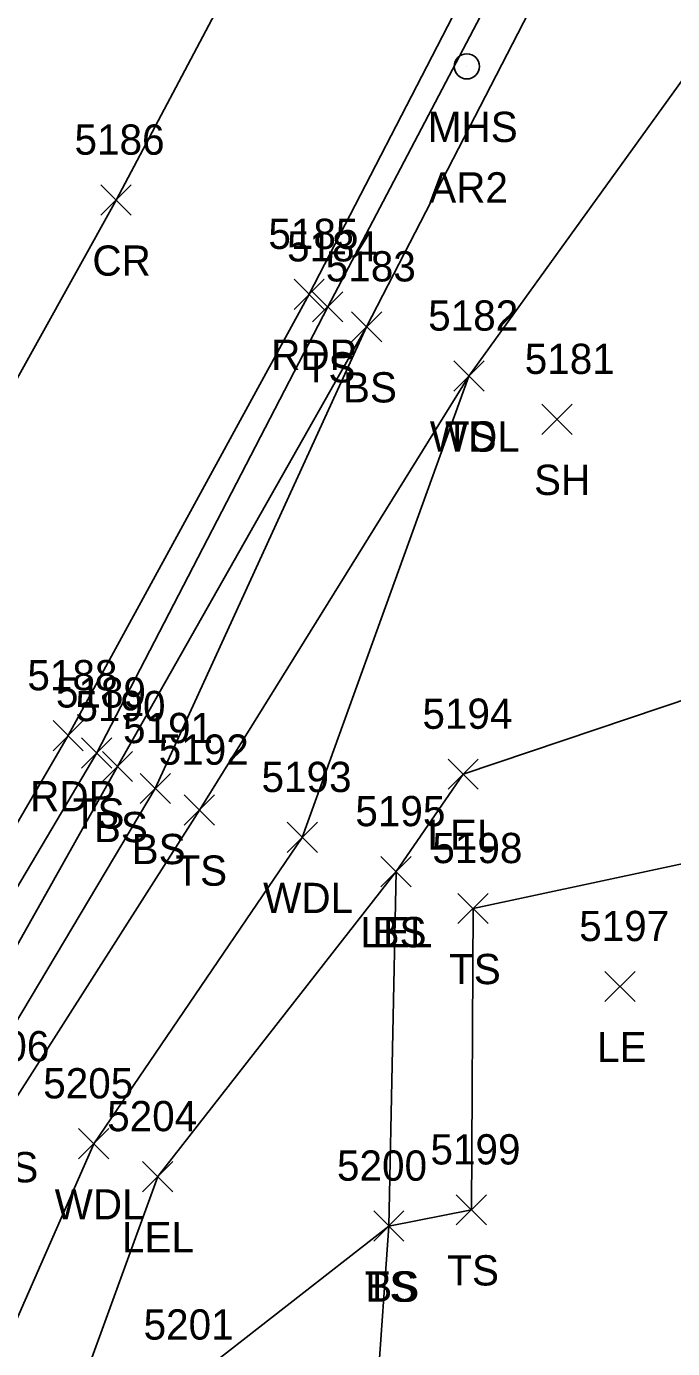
# Model space of a CAD drawing. Extents: x 1678863 to 1683592, y 407783 to 418211.
# Drawn here: x 1679859 to 1679901.7, y 411536.4 to 411623.8 of the extents above; entities that cross this region are included whole.
import ezdxf

# ---------------------------------------------------------------- set-up
doc = ezdxf.new("R2010")
doc.units = 0
for name, color, linetype in [('L_A', 7, 'Continuous'), ('L_I', 7, 'Continuous'), ('L_TIC', 7, 'Continuous'), ('LARO', 7, 'Continuous'), ('LAWA', 7, 'Continuous'), ('LELB', 7, 'Continuous'), ('P_A', 7, 'Continuous'), ('P_I', 7, 'Continuous'), ('P_TIC', 7, 'Continuous'), ('PET', 7, 'Continuous'), ('PRC', 7, 'Continuous'), ('U_A', 7, 'Continuous'), ('U_C', 7, 'Continuous'), ('USMH', 7, 'Continuous')]:
    doc.layers.add(name, color=color, linetype=linetype)

msp = doc.modelspace()

# ---------------------------------------------------------------- linework, layer by layer
at = {"layer": 'L_TIC'}
for points in [[(1679877.886, 411604.221), (1679879.886, 411606.221)], [(1679879.886, 411604.221), (1679877.886, 411606.221)], [(1679880.444, 411602.897), (1679882.444, 411604.897)], [(1679882.444, 411602.897), (1679880.444, 411604.897)], [(1679880.444, 411602.897), (1679882.444, 411604.897)], [(1679882.444, 411602.897), (1679880.444, 411604.897)], [(1679887.208, 411599.645), (1679889.208, 411601.645)], [(1679889.208, 411599.645), (1679887.208, 411601.645)], [(1679887.208, 411599.645), (1679889.208, 411601.645)], [(1679889.208, 411599.645), (1679887.208, 411601.645)], [(1679893.02, 411596.782), (1679895.02, 411598.782)], [(1679895.02, 411596.782), (1679893.02, 411598.782)], [(1679862.627, 411574.73), (1679864.627, 411576.73)], [(1679864.627, 411574.73), (1679862.627, 411576.73)], [(1679863.994, 411573.831), (1679865.994, 411575.831)], [(1679865.994, 411573.831), (1679863.994, 411575.831)], [(1679886.828, 411573.324), (1679888.828, 411575.324)], [(1679888.828, 411573.324), (1679886.828, 411575.324)], [(1679866.487, 411572.377), (1679868.487, 411574.377)], [(1679868.487, 411572.377), (1679866.487, 411574.377)], [(1679869.409, 411570.95), (1679871.409, 411572.95)], [(1679871.409, 411570.95), (1679869.409, 411572.95)], [(1679876.2, 411569.144), (1679878.2, 411571.144)], [(1679878.2, 411569.144), (1679876.2, 411571.144)], [(1679882.398, 411566.885), (1679884.398, 411568.885)], [(1679884.398, 411566.885), (1679882.398, 411568.885)], [(1679882.398, 411566.885), (1679884.398, 411568.885)], [(1679884.398, 411566.885), (1679882.398, 411568.885)], [(1679887.485, 411564.444), (1679889.485, 411566.444)], [(1679889.485, 411564.444), (1679887.485, 411566.444)], [(1679897.183, 411559.29), (1679899.183, 411561.29)], [(1679899.183, 411559.29), (1679897.183, 411561.29)], [(1679862.425, 411548.891), (1679864.425, 411550.891)], [(1679864.425, 411548.891), (1679862.425, 411550.891)], [(1679866.649, 411546.722), (1679868.649, 411548.722)], [(1679868.649, 411546.722), (1679866.649, 411548.722)], [(1679887.367, 411544.524), (1679889.367, 411546.524)], [(1679889.367, 411544.524), (1679887.367, 411546.524)], [(1679881.917, 411543.451), (1679883.917, 411545.451)], [(1679883.917, 411543.451), (1679881.917, 411545.451)], [(1679881.917, 411543.451), (1679883.917, 411545.451)], [(1679883.917, 411543.451), (1679881.917, 411545.451)]]:
    msp.add_lwpolyline(points, dxfattribs=at)
at = {"layer": 'LARO'}
msp.add_lwpolyline([(1679907.503, 411580.963), (1679887.828, 411574.324), (1679883.398, 411567.885), (1679867.649, 411547.722), (1679859.704, 411525.868), (1679858.597, 411519.07), (1679856.94, 411496.975)], dxfattribs=at)
at = {"layer": 'LAWA'}
msp.add_lwpolyline([(1680004.249, 411785.464), (1679976.905, 411753.096), (1679958.04, 411720.983), (1679943.677, 411696.76), (1679930.592, 411672.976), (1679924.115, 411664.991), (1679923.082, 411652.999), (1679912.44, 411634.306), (1679888.208, 411600.645), (1679877.2, 411570.144), (1679863.425, 411549.891), (1679852.513, 411525.045), (1679850.419, 411519.807), (1679839.824, 411505.441), (1679830.057, 411470.344), (1679799.337, 411443.025), (1679785.885, 411428.013), (1679782.745, 411411.852), (1679769.412, 411389.894), (1679761.729, 411378.805), (1679757.565, 411369.696), (1679753.345, 411358.456)], dxfattribs=at)
at = {"layer": 'LELB'}
for points in [[(1679916.516, 411674.282), (1679909.814, 411664.074), (1679898.356, 411642.317), (1679878.886, 411605.221), (1679863.627, 411575.73), (1679852.287, 411556.618), (1679829.81, 411517.044), (1679806.876, 411482.918), (1679785.941, 411449.002), (1679780.561, 411439.673)], [(1679912.886, 411662.567), (1679900.371, 411640.66), (1679881.444, 411603.897), (1679864.994, 411574.831), (1679854.205, 411555.646), (1679832.273, 411515.522), (1679808.936, 411481.732), (1679786.663, 411448.529), (1679780.561, 411439.673)], [(1679881.444, 411603.897), (1679867.487, 411573.377), (1679855.963, 411554.047), (1679841.116, 411527.101), (1679850.419, 411519.807), (1679858.597, 411519.07)], [(1679888.208, 411600.645), (1679870.409, 411571.95), (1679857.937, 411552.344), (1679845.658, 411527.058), (1679852.513, 411525.045), (1679859.704, 411525.868)], [(1679904.651, 411568.894), (1679888.485, 411565.444), (1679888.367, 411545.524), (1679882.917, 411544.451), (1679869.489, 411533.946), (1679866.945, 411496.861)], [(1679883.398, 411567.885), (1679882.917, 411544.451), (1679881.382, 411522.595)]]:
    msp.add_lwpolyline(points, dxfattribs=at)
at = {"layer": 'P_TIC'}
for points in [[(1679863.901, 411611.276), (1679865.901, 411613.276)], [(1679865.901, 411611.276), (1679863.901, 411613.276)], [(1679876.654, 411605.046), (1679878.654, 411607.046)], [(1679878.654, 411605.046), (1679876.654, 411607.046)], [(1679860.735, 411575.871), (1679862.735, 411577.871)], [(1679862.735, 411575.871), (1679860.735, 411577.871)]]:
    msp.add_lwpolyline(points, dxfattribs=at)
at = {"layer": 'PET'}
msp.add_lwpolyline([(1679896.744, 411643.036), (1679877.654, 411606.046), (1679861.735, 411576.871), (1679850.587, 411557.758), (1679827.264, 411518.541), (1679805.428, 411483.788), (1679784.241, 411450.107), (1679753.752, 411395.632), (1679739.592, 411364.36), (1679726.3, 411333.813), (1679713.565, 411299.828), (1679702.729, 411266.533), (1679688.629, 411217.516), (1679676.207, 411170.056), (1679662.503, 411116.261), (1679650.516, 411067.532), (1679638.184, 411018.282), (1679627.73, 410974.874), (1679616.699, 410931.335), (1679604.861, 410884.116), (1679594.891, 410843.787), (1679584.861, 410799.849)], dxfattribs=at)
at = {"layer": 'PRC'}
msp.add_lwpolyline([(1679884.423, 411649.113), (1679864.901, 411612.276), (1679849.333, 411584.209), (1679838.181, 411564.727), (1679814.629, 411525.581), (1679793.157, 411491.355), (1679772.018, 411456.738), (1679754.801, 411427.353), (1679741.755, 411402.459), (1679725.907, 411369.83), (1679712.559, 411339.148), (1679697.19, 411297.012), (1679684.615, 411257.055), (1679672.39, 411213.459), (1679661.84, 411172.032), (1679650.126, 411125.856), (1679638.584, 411078.327), (1679624.742, 411022.941), (1679613.907, 410978.688), (1679602.728, 410933.896), (1679590.952, 410887.12), (1679580.877, 410845.972), (1679570.755, 410804.026)], dxfattribs=at)
at = {"layer": 'USMH'}
for p, q in [((1679888.071, 411621.116), (1679888.071, 411621.116)), ((1679888.905, 411621.116), (1679888.905, 411621.116))]:
    msp.add_line(p, q, dxfattribs=at)
msp.add_circle((1679888.071, 411621.116), 0.833, dxfattribs=at)

# ---------------------------------------------------------------- texts
at = {"layer": 'L_A'}
for s, p in [('TS', (1679877.296, 411600.221)), ('BS', (1679879.885, 411598.897)), ('BS', (1679879.885, 411598.897)), ('WDL', (1679885.625, 411595.645)), ('TS', (1679886.618, 411595.645)), ('SH', (1679892.508, 411592.782)), ('TS', (1679862.036, 411570.73)), ('BS', (1679863.435, 411569.831)), ('LEL', (1679885.466, 411569.324)), ('BS', (1679865.928, 411568.377)), ('TS', (1679868.818, 411566.95)), ('WDL', (1679874.617, 411565.144)), ('LEL', (1679881.035, 411562.885)), ('BS', (1679881.839, 411562.885)), ('TS', (1679886.895, 411560.444)), ('LE', (1679896.671, 411555.29)), ('TS', (1679856.346, 411547.344)), ('WDL', (1679860.842, 411544.891)), ('LEL', (1679865.287, 411542.722)), ('TS', (1679886.776, 411540.524)), ('TS', (1679881.326, 411539.451)), ('BS', (1679881.358, 411539.451))]:
    msp.add_text(s, height=2, dxfattribs=at).set_placement(p)
at = {"layer": 'L_I'}
for s, p in [('5184', (1679876.193, 411608.221)), ('5183', (1679878.751, 411606.897)), ('5183', (1679878.751, 411606.897)), ('5182', (1679885.515, 411603.645)), ('5182', (1679885.515, 411603.645)), ('5181', (1679891.894, 411600.782)), ('5189', (1679860.926, 411578.73)), ('5190', (1679862.215, 411577.831)), ('5194', (1679885.136, 411577.324)), ('5191', (1679865.361, 411576.377)), ('5192', (1679867.716, 411574.95)), ('5193', (1679874.507, 411573.144)), ('5195', (1679880.705, 411570.885)), ('5195', (1679880.705, 411570.885)), ('5198', (1679885.792, 411568.444)), ('5197', (1679895.49, 411563.29)), ('5206', (1679854.543, 411555.344)), ('5205', (1679860.087, 411552.891)), ('5204', (1679864.311, 411550.722)), ('5199', (1679885.666, 411548.524)), ('5200', (1679879.492, 411547.451)), ('5200', (1679879.492, 411547.451)), ('5201', (1679866.717, 411536.946))]:
    msp.add_text(s, height=2, dxfattribs=at).set_placement(p)
at = {"layer": 'P_A'}
for s, p in [('CR', (1679863.334, 411607.276)), ('RDP', (1679875.143, 411601.046)), ('RDP', (1679859.223, 411571.871))]:
    msp.add_text(s, height=2, dxfattribs=at).set_placement(p)
at = {"layer": 'P_I'}
for s, p in [('5186', (1679862.153, 411615.276)), ('5185', (1679874.962, 411609.046)), ('5188', (1679859.042, 411579.871))]:
    msp.add_text(s, height=2, dxfattribs=at).set_placement(p)
at = {"layer": 'U_A'}
msp.add_text('MHS', height=2, dxfattribs=at).set_placement((1679885.489, 411616.116))
at = {"layer": 'U_C'}
msp.add_text('AR2', height=2, dxfattribs=at).set_placement((1679885.583, 411612.116))

doc.saveas('drawing.dxf')
